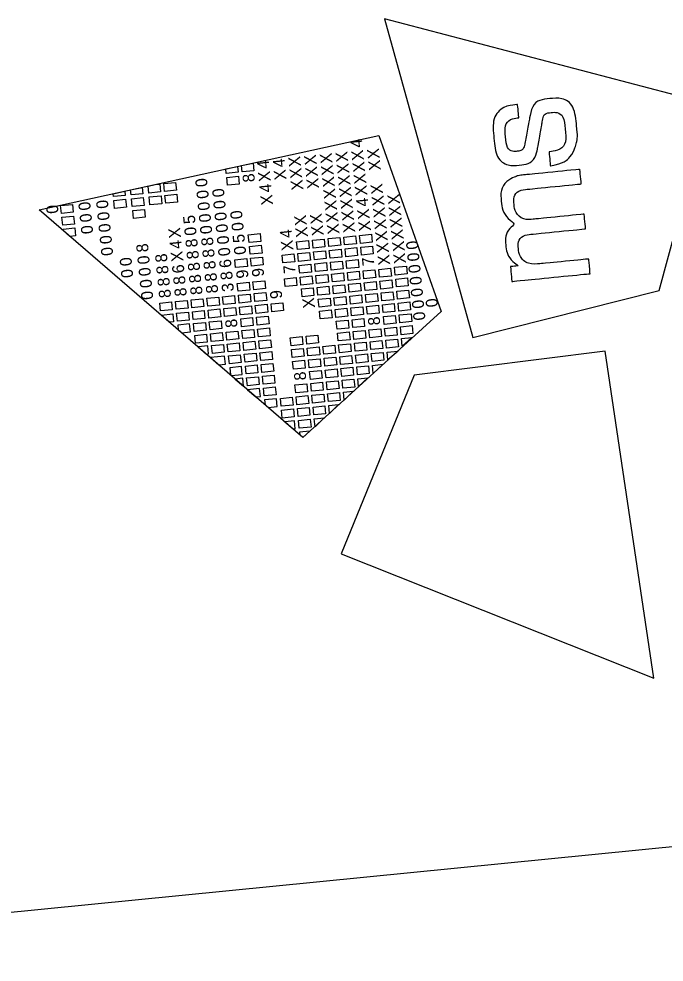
# Model space of a CAD drawing. Extents: x 2210919 to 2211172, y 637144 to 637504.
# Drawn here: x 2211098.3 to 2211107.28, y 637479.69 to 637492.81 of the extents above; entities that cross this region are included whole.
import ezdxf

# ---------------------------------------------------------------- set-up
doc = ezdxf.new("R2010")
doc.units = 0
doc.layers.add('SH_Border', color=7, linetype='Continuous')
doc.layers.add('SH_Data', color=7, linetype='Continuous')

msp = doc.modelspace()

# ---------------------------------------------------------------- linework, layer by layer
at = {"layer": 'SH_Border'}
for p, q in [((2211098.582, 637490.154), (2211103.312, 637491.191)), ((2211103.312, 637491.191), (2211104.18, 637488.742)), ((2211098.582, 637490.154), (2211098.582, 637490.154)), ((2211102.254, 637486.989), (2211098.582, 637490.154)), ((2211104.18, 637488.742), (2211102.254, 637486.989)), ((2211135.224, 637484.055), (2210926.251, 637463.317))]:
    msp.add_line(p, q, dxfattribs=at)
for points in [[(2211107.921, 637491.625), (2211103.389, 637492.813), (2211104.619, 637488.378), (2211107.214, 637489.035), (2211107.921, 637491.625)], [(2211100.511, 637488.551), (2211100.518, 637488.485), (2211100.563, 637488.446), (2211100.687, 637488.458), (2211100.676, 637488.568), (2211100.511, 637488.551)], [(2211100.793, 637488.248), (2211100.909, 637488.148), (2211100.938, 637488.151), (2211100.928, 637488.261), (2211100.793, 637488.248)], [(2211100.966, 637488.099), (2211101.081, 637488), (2211101.174, 637488.009), (2211101.163, 637488.118), (2211100.966, 637488.099)], [(2211102.787, 637485.37), (2211107.141, 637483.639), (2211106.461, 637488.191), (2211103.804, 637487.855), (2211102.787, 637485.37)], [(2211101.234, 637487.959), (2211101.244, 637487.859), (2211101.254, 637487.851), (2211101.409, 637487.866), (2211101.398, 637487.976), (2211101.234, 637487.959)], [(2211101.311, 637487.801), (2211101.425, 637487.703), (2211101.415, 637487.811), (2211101.311, 637487.801)], [(2211101.484, 637487.652), (2211101.599, 637487.553), (2211101.661, 637487.559), (2211101.65, 637487.669), (2211101.484, 637487.652)], [(2211101.721, 637487.51), (2211101.728, 637487.442), (2211101.772, 637487.404), (2211101.896, 637487.417), (2211101.886, 637487.526), (2211101.721, 637487.51)], [(2211102.002, 637487.206), (2211102.117, 637487.107), (2211102.148, 637487.11), (2211102.137, 637487.219), (2211102.002, 637487.206)], [(2211102.208, 637487.06), (2211102.212, 637487.025), (2211102.254, 637486.989), (2211102.348, 637487.074), (2211102.208, 637487.06)]]:
    msp.add_lwpolyline(points, dxfattribs=at)
for points in [[(2211101.187, 637490.661), (2211101.181, 637490.724), (2211101.343, 637490.759), (2211101.351, 637490.678)], [(2211101.406, 637490.683), (2211101.397, 637490.771), (2211101.56, 637490.807), (2211101.57, 637490.699)], [(2211101.203, 637490.497), (2211101.192, 637490.607), (2211101.357, 637490.623), (2211101.368, 637490.514)], [(2211099.861, 637490.364), (2211099.854, 637490.433), (2211100.017, 637490.468), (2211100.026, 637490.38)], [(2211100.108, 637490.389), (2211100.098, 637490.486), (2211100.197, 637490.508), (2211100.261, 637490.514), (2211100.272, 637490.405)], [(2211100.327, 637490.41), (2211100.316, 637490.52), (2211100.48, 637490.536), (2211100.491, 637490.427)], [(2211099.615, 637490.34), (2211099.611, 637490.379), (2211099.773, 637490.415), (2211099.779, 637490.356)], [(2211099.878, 637490.2), (2211099.867, 637490.31), (2211100.031, 637490.326), (2211100.042, 637490.216)], [(2211100.124, 637490.225), (2211100.113, 637490.334), (2211100.278, 637490.351), (2211100.288, 637490.241)], [(2211100.343, 637490.246), (2211100.332, 637490.356), (2211100.497, 637490.372), (2211100.507, 637490.263)], [(2211098.891, 637490.105), (2211098.88, 637490.215), (2211099.045, 637490.231), (2211099.056, 637490.122)], [(2211099.631, 637490.176), (2211099.62, 637490.285), (2211099.785, 637490.302), (2211099.795, 637490.192)], [(2211098.908, 637489.941), (2211098.897, 637490.051), (2211099.061, 637490.067), (2211099.072, 637489.957)], [(2211099.894, 637490.036), (2211099.883, 637490.146), (2211100.047, 637490.162), (2211100.058, 637490.053)], [(2211099.009, 637489.786), (2211098.915, 637489.866), (2211098.913, 637489.887), (2211099.077, 637489.903), (2211099.088, 637489.793)], [(2211101.504, 637489.7), (2211101.493, 637489.809), (2211101.657, 637489.825), (2211101.668, 637489.716)], [(2211102.835, 637489.667), (2211102.824, 637489.777), (2211102.988, 637489.793), (2211102.999, 637489.683)], [(2211103.054, 637489.689), (2211103.043, 637489.798), (2211103.207, 637489.815), (2211103.218, 637489.705)], [(2211101.52, 637489.537), (2211101.509, 637489.646), (2211101.673, 637489.662), (2211101.684, 637489.553)], [(2211102.177, 637489.602), (2211102.166, 637489.711), (2211102.331, 637489.728), (2211102.342, 637489.618)], [(2211102.396, 637489.624), (2211102.386, 637489.733), (2211102.55, 637489.749), (2211102.561, 637489.64)], [(2211102.615, 637489.645), (2211102.605, 637489.755), (2211102.769, 637489.771), (2211102.78, 637489.662)], [(2211101.974, 637489.416), (2211101.964, 637489.525), (2211102.128, 637489.542), (2211102.139, 637489.432)], [(2211102.194, 637489.438), (2211102.183, 637489.547), (2211102.347, 637489.563), (2211102.358, 637489.454)], [(2211102.413, 637489.459), (2211102.402, 637489.569), (2211102.566, 637489.585), (2211102.577, 637489.476)], [(2211102.632, 637489.481), (2211102.621, 637489.591), (2211102.785, 637489.607), (2211102.796, 637489.497)], [(2211102.851, 637489.503), (2211102.84, 637489.612), (2211103.004, 637489.629), (2211103.015, 637489.519)], [(2211103.07, 637489.525), (2211103.059, 637489.634), (2211103.223, 637489.65), (2211103.234, 637489.541)], [(2211101.317, 637489.351), (2211101.306, 637489.46), (2211101.471, 637489.476), (2211101.482, 637489.367)], [(2211101.536, 637489.372), (2211101.525, 637489.482), (2211101.69, 637489.498), (2211101.701, 637489.389)], [(2211102.21, 637489.273), (2211102.199, 637489.383), (2211102.363, 637489.399), (2211102.374, 637489.29)], [(2211102.429, 637489.295), (2211102.418, 637489.405), (2211102.582, 637489.421), (2211102.593, 637489.311)], [(2211102.648, 637489.317), (2211102.637, 637489.426), (2211102.802, 637489.443), (2211102.812, 637489.333)], [(2211102.867, 637489.338), (2211102.856, 637489.448), (2211103.021, 637489.464), (2211103.032, 637489.355)], [(2211102.664, 637489.152), (2211102.654, 637489.262), (2211102.818, 637489.278), (2211102.829, 637489.169)], [(2211102.884, 637489.174), (2211102.873, 637489.284), (2211103.037, 637489.3), (2211103.048, 637489.19)], [(2211103.103, 637489.196), (2211103.092, 637489.305), (2211103.256, 637489.322), (2211103.267, 637489.212)], [(2211103.322, 637489.218), (2211103.311, 637489.327), (2211103.475, 637489.344), (2211103.486, 637489.234)], [(2211103.54, 637489.248), (2211103.529, 637489.357), (2211103.694, 637489.373), (2211103.704, 637489.264)], [(2211101.35, 637489.022), (2211101.339, 637489.131), (2211101.503, 637489.148), (2211101.514, 637489.038)], [(2211101.569, 637489.044), (2211101.558, 637489.153), (2211101.722, 637489.169), (2211101.733, 637489.06)], [(2211102.007, 637489.087), (2211101.996, 637489.197), (2211102.161, 637489.213), (2211102.171, 637489.103)], [(2211102.226, 637489.109), (2211102.215, 637489.218), (2211102.38, 637489.235), (2211102.391, 637489.125)], [(2211102.445, 637489.131), (2211102.434, 637489.24), (2211102.599, 637489.257), (2211102.61, 637489.147)], [(2211102.9, 637489.01), (2211102.889, 637489.119), (2211103.053, 637489.136), (2211103.064, 637489.026)], [(2211103.119, 637489.032), (2211103.108, 637489.141), (2211103.272, 637489.157), (2211103.283, 637489.048)], [(2211103.338, 637489.053), (2211103.327, 637489.163), (2211103.492, 637489.179), (2211103.502, 637489.07)], [(2211103.557, 637489.082), (2211103.546, 637489.191), (2211103.71, 637489.208), (2211103.721, 637489.098)], [(2211101.585, 637488.879), (2211101.574, 637488.989), (2211101.739, 637489.005), (2211101.75, 637488.896)], [(2211102.243, 637488.945), (2211102.232, 637489.054), (2211102.396, 637489.07), (2211102.407, 637488.961)], [(2211102.462, 637488.966), (2211102.451, 637489.076), (2211102.615, 637489.092), (2211102.626, 637488.983)], [(2211102.681, 637488.988), (2211102.67, 637489.098), (2211102.834, 637489.114), (2211102.845, 637489.004)], [(2211103.354, 637488.889), (2211103.344, 637488.999), (2211103.508, 637489.015), (2211103.519, 637488.905)], [(2211103.573, 637488.913), (2211103.562, 637489.023), (2211103.726, 637489.039), (2211103.737, 637488.93)], [(2211100.271, 637488.749), (2211100.26, 637488.858), (2211100.424, 637488.875), (2211100.435, 637488.765)], [(2211100.49, 637488.771), (2211100.479, 637488.88), (2211100.643, 637488.896), (2211100.654, 637488.787)], [(2211100.709, 637488.792), (2211100.698, 637488.902), (2211100.862, 637488.918), (2211100.873, 637488.809)], [(2211100.928, 637488.814), (2211100.917, 637488.924), (2211101.081, 637488.94), (2211101.092, 637488.83)], [(2211101.147, 637488.836), (2211101.136, 637488.945), (2211101.3, 637488.962), (2211101.311, 637488.852)], [(2211101.366, 637488.858), (2211101.355, 637488.967), (2211101.52, 637488.983), (2211101.53, 637488.874)], [(2211102.478, 637488.802), (2211102.467, 637488.912), (2211102.631, 637488.928), (2211102.642, 637488.818)], [(2211102.697, 637488.824), (2211102.686, 637488.933), (2211102.851, 637488.95), (2211102.861, 637488.84)], [(2211102.916, 637488.845), (2211102.905, 637488.955), (2211103.07, 637488.971), (2211103.081, 637488.862)], [(2211103.135, 637488.867), (2211103.124, 637488.977), (2211103.289, 637488.993), (2211103.3, 637488.884)], [(2211103.589, 637488.747), (2211103.578, 637488.857), (2211103.743, 637488.873), (2211103.753, 637488.764)], [(2211100.725, 637488.628), (2211100.714, 637488.737), (2211100.879, 637488.754), (2211100.889, 637488.644)], [(2211100.944, 637488.65), (2211100.933, 637488.759), (2211101.098, 637488.776), (2211101.109, 637488.666)], [(2211101.163, 637488.671), (2211101.152, 637488.781), (2211101.317, 637488.797), (2211101.328, 637488.688)], [(2211101.382, 637488.693), (2211101.372, 637488.803), (2211101.536, 637488.819), (2211101.547, 637488.71)], [(2211101.602, 637488.715), (2211101.591, 637488.825), (2211101.755, 637488.841), (2211101.766, 637488.731)], [(2211101.821, 637488.737), (2211101.81, 637488.846), (2211101.974, 637488.863), (2211101.985, 637488.753)], [(2211102.494, 637488.638), (2211102.483, 637488.747), (2211102.648, 637488.764), (2211102.659, 637488.654)], [(2211102.713, 637488.659), (2211102.703, 637488.769), (2211102.867, 637488.785), (2211102.878, 637488.676)], [(2211102.932, 637488.681), (2211102.922, 637488.791), (2211103.086, 637488.807), (2211103.097, 637488.697)], [(2211103.152, 637488.703), (2211103.141, 637488.812), (2211103.305, 637488.829), (2211103.316, 637488.719)], [(2211103.371, 637488.725), (2211103.36, 637488.834), (2211103.524, 637488.851), (2211103.535, 637488.741)], [(2211100.395, 637488.591), (2211100.28, 637488.69), (2211100.441, 637488.706), (2211100.452, 637488.597)], [(2211100.506, 637488.606), (2211100.495, 637488.716), (2211100.659, 637488.732), (2211100.67, 637488.622)], [(2211100.961, 637488.485), (2211100.95, 637488.595), (2211101.114, 637488.611), (2211101.125, 637488.502)], [(2211101.399, 637488.529), (2211101.388, 637488.638), (2211101.552, 637488.655), (2211101.563, 637488.545)], [(2211101.618, 637488.551), (2211101.607, 637488.66), (2211101.771, 637488.676), (2211101.782, 637488.567)], [(2211102.73, 637488.495), (2211102.719, 637488.605), (2211102.883, 637488.621), (2211102.894, 637488.511)], [(2211102.949, 637488.517), (2211102.938, 637488.626), (2211103.102, 637488.643), (2211103.113, 637488.533)], [(2211103.387, 637488.56), (2211103.376, 637488.67), (2211103.54, 637488.686), (2211103.551, 637488.577)], [(2211103.605, 637488.584), (2211103.594, 637488.694), (2211103.759, 637488.71), (2211103.77, 637488.601)], [(2211100.741, 637488.464), (2211100.731, 637488.573), (2211100.895, 637488.589), (2211100.906, 637488.48)], [(2211101.415, 637488.365), (2211101.404, 637488.474), (2211101.569, 637488.49), (2211101.579, 637488.381)], [(2211101.634, 637488.386), (2211101.623, 637488.496), (2211101.788, 637488.512), (2211101.799, 637488.403)], [(2211102.965, 637488.352), (2211102.954, 637488.462), (2211103.119, 637488.478), (2211103.129, 637488.369)], [(2211103.184, 637488.374), (2211103.173, 637488.484), (2211103.338, 637488.5), (2211103.349, 637488.391)], [(2211103.403, 637488.396), (2211103.392, 637488.506), (2211103.557, 637488.522), (2211103.568, 637488.412)], [(2211103.622, 637488.418), (2211103.611, 637488.528), (2211103.775, 637488.544), (2211103.786, 637488.435)], [(2211100.758, 637488.299), (2211100.747, 637488.409), (2211100.911, 637488.425), (2211100.922, 637488.316)], [(2211100.977, 637488.321), (2211100.966, 637488.431), (2211101.13, 637488.447), (2211101.141, 637488.337)], [(2211101.196, 637488.343), (2211101.185, 637488.452), (2211101.349, 637488.469), (2211101.36, 637488.359)], [(2211101.65, 637488.222), (2211101.64, 637488.332), (2211101.804, 637488.348), (2211101.815, 637488.238)], [(2211102.089, 637488.265), (2211102.078, 637488.375), (2211102.242, 637488.391), (2211102.253, 637488.282)], [(2211102.308, 637488.287), (2211102.297, 637488.397), (2211102.461, 637488.413), (2211102.472, 637488.304)], [(2211102.746, 637488.331), (2211102.735, 637488.44), (2211102.899, 637488.457), (2211102.91, 637488.347)], [(2211103.42, 637488.232), (2211103.409, 637488.341), (2211103.573, 637488.358), (2211103.584, 637488.248)], [(2211103.638, 637488.258), (2211103.627, 637488.363), (2211103.769, 637488.378)], [(2211100.993, 637488.157), (2211100.982, 637488.266), (2211101.147, 637488.283), (2211101.158, 637488.173)], [(2211101.212, 637488.178), (2211101.201, 637488.288), (2211101.366, 637488.304), (2211101.377, 637488.195)], [(2211101.431, 637488.2), (2211101.421, 637488.31), (2211101.585, 637488.326), (2211101.596, 637488.217)], [(2211102.105, 637488.101), (2211102.094, 637488.211), (2211102.258, 637488.227), (2211102.269, 637488.117)], [(2211102.324, 637488.123), (2211102.313, 637488.232), (2211102.478, 637488.249), (2211102.488, 637488.139)], [(2211102.543, 637488.145), (2211102.532, 637488.254), (2211102.697, 637488.271), (2211102.708, 637488.161)], [(2211102.762, 637488.166), (2211102.751, 637488.276), (2211102.916, 637488.292), (2211102.927, 637488.183)], [(2211102.981, 637488.188), (2211102.971, 637488.298), (2211103.135, 637488.314), (2211103.146, 637488.204)], [(2211103.201, 637488.21), (2211103.19, 637488.319), (2211103.354, 637488.336), (2211103.365, 637488.226)], [(2211101.229, 637488.014), (2211101.218, 637488.124), (2211101.382, 637488.14), (2211101.393, 637488.03)], [(2211101.448, 637488.036), (2211101.437, 637488.145), (2211101.601, 637488.162), (2211101.612, 637488.052)], [(2211101.667, 637488.058), (2211101.656, 637488.167), (2211101.82, 637488.184), (2211101.831, 637488.074)], [(2211102.34, 637487.959), (2211102.33, 637488.068), (2211102.494, 637488.084), (2211102.505, 637487.975)], [(2211102.56, 637487.98), (2211102.549, 637488.09), (2211102.713, 637488.106), (2211102.724, 637487.997)], [(2211102.779, 637488.002), (2211102.768, 637488.112), (2211102.932, 637488.128), (2211102.943, 637488.018)], [(2211102.998, 637488.024), (2211102.987, 637488.133), (2211103.151, 637488.15), (2211103.162, 637488.04)], [(2211103.217, 637488.046), (2211103.206, 637488.155), (2211103.37, 637488.171), (2211103.381, 637488.062)], [(2211103.579, 637488.19), (2211103.436, 637488.067), (2211103.425, 637488.176)], [(2211101.464, 637487.872), (2211101.453, 637487.981), (2211101.617, 637487.997), (2211101.628, 637487.888)], [(2211101.683, 637487.893), (2211101.672, 637488.003), (2211101.837, 637488.019), (2211101.847, 637487.91)], [(2211102.121, 637487.937), (2211102.11, 637488.046), (2211102.275, 637488.063), (2211102.286, 637487.953)], [(2211102.795, 637487.838), (2211102.784, 637487.947), (2211102.948, 637487.964), (2211102.959, 637487.854)], [(2211103.014, 637487.86), (2211103.003, 637487.969), (2211103.168, 637487.985), (2211103.178, 637487.876)], [(2211103.373, 637488.006), (2211103.233, 637487.88), (2211103.222, 637487.991)], [(2211101.48, 637487.707), (2211101.469, 637487.817), (2211101.634, 637487.833), (2211101.645, 637487.724)], [(2211101.699, 637487.729), (2211101.689, 637487.839), (2211101.853, 637487.855), (2211101.864, 637487.745)], [(2211102.357, 637487.794), (2211102.346, 637487.904), (2211102.51, 637487.92), (2211102.521, 637487.811)], [(2211102.576, 637487.816), (2211102.565, 637487.926), (2211102.729, 637487.942), (2211102.74, 637487.832)], [(2211101.716, 637487.565), (2211101.705, 637487.674), (2211101.869, 637487.691), (2211101.88, 637487.581)], [(2211102.154, 637487.608), (2211102.143, 637487.718), (2211102.307, 637487.734), (2211102.318, 637487.624)], [(2211102.373, 637487.63), (2211102.362, 637487.739), (2211102.527, 637487.756), (2211102.537, 637487.646)], [(2211102.592, 637487.652), (2211102.581, 637487.761), (2211102.746, 637487.778), (2211102.757, 637487.668)], [(2211102.811, 637487.673), (2211102.8, 637487.783), (2211102.965, 637487.799), (2211102.976, 637487.69)], [(2211103.03, 637487.695), (2211103.02, 637487.805), (2211103.156, 637487.818)], [(2211102.17, 637487.444), (2211102.159, 637487.553), (2211102.324, 637487.57), (2211102.335, 637487.46)], [(2211102.389, 637487.466), (2211102.379, 637487.575), (2211102.543, 637487.591), (2211102.554, 637487.482)], [(2211102.608, 637487.487), (2211102.598, 637487.597), (2211102.762, 637487.613), (2211102.773, 637487.504)], [(2211102.828, 637487.509), (2211102.817, 637487.619), (2211102.954, 637487.632)], [(2211102.817, 637487.619), (2211102.817, 637487.619), (2211102.817, 637487.619)], [(2211101.951, 637487.422), (2211101.94, 637487.532), (2211102.105, 637487.548), (2211102.116, 637487.438)], [(2211102.406, 637487.301), (2211102.395, 637487.411), (2211102.559, 637487.427), (2211102.57, 637487.318)], [(2211102.625, 637487.323), (2211102.614, 637487.433), (2211102.751, 637487.446)], [(2211101.967, 637487.258), (2211101.957, 637487.367), (2211102.121, 637487.384), (2211102.132, 637487.274)], [(2211102.187, 637487.28), (2211102.176, 637487.389), (2211102.34, 637487.405), (2211102.351, 637487.296)], [(2211102.203, 637487.115), (2211102.192, 637487.225), (2211102.356, 637487.241), (2211102.367, 637487.131)], [(2211102.422, 637487.137), (2211102.411, 637487.246), (2211102.548, 637487.26)]]:
    msp.add_lwpolyline(points, close=True, dxfattribs=at)
for points in [[(2211105.708, 637490.769), (2211105.708, 637490.769), (2211105.7, 637490.767), (2211105.7, 637490.767), (2211105.7, 637490.767), (2211105.699, 637490.775), (2211105.699, 637490.775), (2211105.699, 637490.775), (2211105.682, 637490.954), (2211105.682, 637490.954), (2211105.682, 637490.954), (2211105.681, 637490.961), (2211105.681, 637490.961), (2211105.681, 637490.961), (2211105.688, 637490.962), (2211105.688, 637490.962), (2211105.842, 637490.99), (2211105.927, 637491.083), (2211105.907, 637491.285), (2211105.889, 637491.467), (2211105.789, 637491.518), (2211105.713, 637491.51), (2211105.612, 637491.5), (2211105.594, 637491.421), (2211105.58, 637491.338), (2211105.58, 637491.338), (2211105.524, 637491.026), (2211105.524, 637491.026), (2211105.496, 637490.873), (2211105.395, 637490.79), (2211105.272, 637490.778), (2211105.112, 637490.762), (2211104.942, 637490.866), (2211104.914, 637491.149), (2211104.885, 637491.443), (2211105.047, 637491.601), (2211105.236, 637491.62), (2211105.236, 637491.62), (2211105.243, 637491.62), (2211105.243, 637491.62), (2211105.243, 637491.62), (2211105.244, 637491.613), (2211105.244, 637491.613), (2211105.244, 637491.613), (2211105.261, 637491.444), (2211105.261, 637491.444), (2211105.261, 637491.444), (2211105.261, 637491.437), (2211105.261, 637491.437), (2211105.261, 637491.437), (2211105.254, 637491.436), (2211105.254, 637491.436), (2211105.141, 637491.422), (2211105.058, 637491.338), (2211105.075, 637491.168), (2211105.091, 637491.004), (2211105.177, 637490.964), (2211105.238, 637490.97), (2211105.287, 637490.975), (2211105.332, 637491.006), (2211105.349, 637491.098), (2211105.349, 637491.098), (2211105.405, 637491.401), (2211105.405, 637491.401), (2211105.443, 637491.613), (2211105.548, 637491.689), (2211105.685, 637491.702), (2211105.861, 637491.72), (2211106.036, 637491.619), (2211106.068, 637491.298), (2211106.081, 637491.164), (2211106.066, 637491.087), (2211106.045, 637491.03), (2211105.992, 637490.892), (2211105.879, 637490.799), (2211105.708, 637490.769)], [(2211106.253, 637489.267), (2211106.253, 637489.267), (2211105.164, 637489.159), (2211105.164, 637489.159), (2211105.164, 637489.159), (2211105.144, 637489.365), (2211105.144, 637489.365), (2211105.144, 637489.365), (2211105.255, 637489.376), (2211105.255, 637489.376), (2211105.144, 637489.457), (2211105.088, 637489.563), (2211105.079, 637489.661), (2211105.066, 637489.793), (2211105.128, 637489.903), (2211105.228, 637489.958), (2211105.107, 637490.025), (2211105.028, 637490.153), (2211105.017, 637490.268), (2211105.001, 637490.427), (2211105.084, 637490.561), (2211105.217, 637490.618), (2211105.217, 637490.618), (2211105.218, 637490.618), (2211105.218, 637490.618), (2211105.239, 637490.627), (2211105.256, 637490.634), (2211105.357, 637490.644), (2211105.357, 637490.644), (2211106.109, 637490.719), (2211106.109, 637490.719), (2211106.109, 637490.719), (2211106.13, 637490.516), (2211106.13, 637490.516), (2211106.13, 637490.516), (2211105.4, 637490.444), (2211105.4, 637490.444), (2211105.247, 637490.429), (2211105.183, 637490.338), (2211105.194, 637490.23), (2211105.205, 637490.115), (2211105.319, 637490.01), (2211105.488, 637490.027), (2211105.488, 637490.027), (2211106.171, 637490.095), (2211106.171, 637490.095), (2211106.171, 637490.095), (2211106.191, 637489.891), (2211106.191, 637489.891), (2211106.191, 637489.891), (2211105.45, 637489.817), (2211105.45, 637489.817), (2211105.307, 637489.803), (2211105.245, 637489.71), (2211105.254, 637489.619), (2211105.265, 637489.507), (2211105.381, 637489.388), (2211105.589, 637489.408), (2211105.589, 637489.408), (2211106.233, 637489.472), (2211106.233, 637489.472), (2211106.233, 637489.472), (2211106.253, 637489.267), (2211106.253, 637489.267)]]:
    msp.add_open_spline(points, degree=3, dxfattribs=at)
at = {"layer": 'SH_Data'}
msp.add_line((2211104.63, 637488.556), (2211104.63, 637488.556), dxfattribs=at)

# ---------------------------------------------------------------- texts
at = {"layer": 'SH_Border'}
for s, p in [('4', (2211103.087, 637491.027)), ('X', (2211103.104, 637490.849)), ('X', (2211103.324, 637490.871)), ('4', (2211101.789, 637490.732)), ('4', (2211102.008, 637490.754)), ('X', (2211102.228, 637490.762)), ('X', (2211102.447, 637490.784)), ('X', (2211102.666, 637490.806)), ('X', (2211102.885, 637490.828)), ('X', (2211103.34, 637490.71)), ('X', (2211102.025, 637490.577)), ('X', (2211102.244, 637490.599)), ('X', (2211102.463, 637490.62)), ('X', (2211102.682, 637490.642)), ('X', (2211102.902, 637490.664)), ('X', (2211103.121, 637490.686)), ('0', (2211100.928, 637490.481)), ('8', (2211101.586, 637490.546)), ('X', (2211101.806, 637490.555)), ('X', (2211102.48, 637490.456)), ('X', (2211102.699, 637490.478)), ('X', (2211102.918, 637490.5)), ('X', (2211103.137, 637490.522)), ('0', (2211101.164, 637490.339)), ('4', (2211101.821, 637490.404)), ('X', (2211102.261, 637490.435)), ('X', (2211102.715, 637490.314)), ('X', (2211102.934, 637490.336)), ('X', (2211103.153, 637490.358)), ('X', (2211103.372, 637490.38)), ('0', (2211100.945, 637490.317)), ('X', (2211101.839, 637490.227)), ('4', (2211103.168, 637490.207)), ('X', (2211103.389, 637490.216)), ('X', (2211103.608, 637490.237)), ('0', (2211098.852, 637490.109)), ('0', (2211099.301, 637490.154)), ('0', (2211099.548, 637490.179)), ('0', (2211100.961, 637490.153)), ('0', (2211101.18, 637490.175)), ('X', (2211102.731, 637490.15)), ('X', (2211102.95, 637490.172)), ('X', (2211103.405, 637490.052)), ('X', (2211103.624, 637490.073)), ('0', (2211099.318, 637489.99)), ('0', (2211099.564, 637490.015)), ('5', (2211100.759, 637489.967)), ('0', (2211100.977, 637489.989)), ('0', (2211101.196, 637490.011)), ('0', (2211101.415, 637490.033)), ('X', (2211102.309, 637489.943)), ('X', (2211102.528, 637489.965)), ('X', (2211102.748, 637489.986)), ('X', (2211102.967, 637490.008)), ('X', (2211103.186, 637490.03)), ('0', (2211099.334, 637489.826)), ('0', (2211099.58, 637489.851)), ('0', (2211100.993, 637489.826)), ('0', (2211101.213, 637489.847)), ('0', (2211101.432, 637489.869)), ('X', (2211102.326, 637489.779)), ('X', (2211102.545, 637489.801)), ('X', (2211102.764, 637489.823)), ('X', (2211102.983, 637489.844)), ('X', (2211103.202, 637489.866)), ('X', (2211103.421, 637489.888)), ('X', (2211103.64, 637489.91)), ('0', (2211099.597, 637489.687)), ('X', (2211100.557, 637489.769)), ('0', (2211100.775, 637489.804)), ('0', (2211101.229, 637489.683)), ('5', (2211101.448, 637489.704)), ('4', (2211102.105, 637489.77)), ('X', (2211103.437, 637489.724)), ('X', (2211103.657, 637489.746)), ('8', (2211100.106, 637489.572)), ('4', (2211100.571, 637489.618)), ('8', (2211100.791, 637489.64)), ('8', (2211101.01, 637489.661)), ('X', (2211102.123, 637489.594)), ('X', (2211103.454, 637489.56)), ('X', (2211103.673, 637489.582)), ('0', (2211103.864, 637489.61)), ('0', (2211099.613, 637489.523)), ('8', (2211100.369, 637489.432)), ('X', (2211100.589, 637489.442)), ('8', (2211100.807, 637489.476)), ('8', (2211101.026, 637489.498)), ('0', (2211101.245, 637489.519)), ('0', (2211101.465, 637489.538)), ('X', (2211103.47, 637489.392)), ('X', (2211103.689, 637489.414)), ('0', (2211103.88, 637489.446)), ('0', (2211099.876, 637489.38)), ('0', (2211100.122, 637489.405)), ('8', (2211100.824, 637489.312)), ('8', (2211101.042, 637489.334)), ('6', (2211101.261, 637489.355)), ('7', (2211103.25, 637489.383)), ('0', (2211099.892, 637489.216)), ('0', (2211100.139, 637489.24)), ('8', (2211100.385, 637489.268)), ('6', (2211100.605, 637489.28)), ('8', (2211101.059, 637489.166)), ('8', (2211101.278, 637489.187)), ('9', (2211101.497, 637489.209)), ('9', (2211101.716, 637489.231)), ('7', (2211102.154, 637489.275)), ('0', (2211103.896, 637489.282)), ('0', (2211100.155, 637489.076)), ('8', (2211100.402, 637489.1)), ('8', (2211100.621, 637489.122)), ('8', (2211100.84, 637489.144)), ('3', (2211101.294, 637489.023)), ('0', (2211103.913, 637489.117)), ('0', (2211100.171, 637488.912)), ('8', (2211100.418, 637488.936)), ('8', (2211100.637, 637488.958)), ('8', (2211100.857, 637488.98)), ('8', (2211101.075, 637489.001)), ('9', (2211101.968, 637488.924)), ('0', (2211103.929, 637488.953)), ('X', (2211102.423, 637488.794)), ('0', (2211103.945, 637488.789)), ('0', (2211104.136, 637488.808)), ('8', (2211101.344, 637488.523)), ('8', (2211103.332, 637488.555)), ('0', (2211103.961, 637488.624)), ('8', (2211102.302, 637487.789))]:
    msp.add_text(s, height=0.165, rotation=95.6702, dxfattribs=at).set_placement(p)

doc.saveas('drawing.dxf')
